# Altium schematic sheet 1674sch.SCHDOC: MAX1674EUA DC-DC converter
size 152 x 114 mm; Author: Harrylee
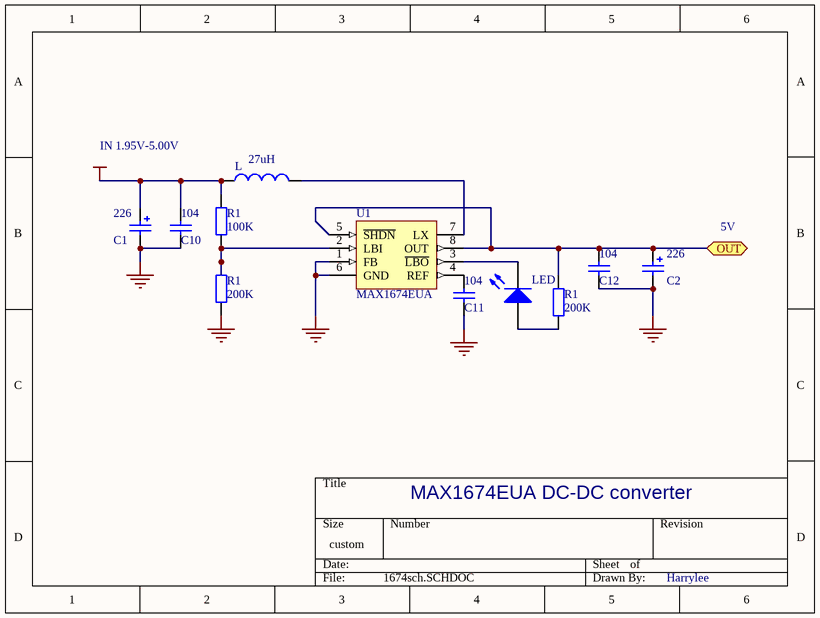
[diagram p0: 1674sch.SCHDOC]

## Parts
(Parts that share a designator on the sheet are numbered #1, #2 ... from top to bottom, then left to right.)
C1  value 226  [RB7.6-15]  (hidden comment: Cap Pol1)
C2  value 226  [RB7.6-15]  (hidden comment: Cap Pol1)
C10  value 104  [CC1310-0504]  (hidden comment: Cap Semi)
C11  value 104  [CC1310-0504]  (hidden comment: Cap Semi)
C12  value 104  [CC1310-0504]  (hidden comment: Cap Semi)
L  value 27uH  [CC4532-1812]  (hidden comment: Inductor)
LED  LED2  [DSO-F2/D6.1]  (value not drawn)
R1#1  value 100K  [AXIAL-0.4]  (hidden comment: Res2)
R1#2  value 200K  [AXIAL-0.4]  (hidden comment: Res2)
R1#3  value 200K  [AXIAL-0.4]  (hidden comment: Res2)
U1  MAX1674EUA  [UMAX8]

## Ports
OUT

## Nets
GND: C1.2 C2.2 C10.1 C11.1 C12.1 R1#2.1 U1.1(FB) U1.6(GND)
VCC: C1.1 C10.2 L.1 R1#1.1
OUT: C2.1 C12.2 R1#3.2 U1.5(~{SHDN}) U1.8(OUT) ; port OUT
NetC11_2: C11.2 U1.4(REF)
NetL_2: L.2 U1.7(LX)
NetLED_1: LED.1(A) R1#3.1
NetLED_2: LED.2(K) U1.3(~{LBO})
NetR1#1_2: R1#1.2 R1#2.2 U1.2(LBI)

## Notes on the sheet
- IN 1.95V-5.00V
- 5V
- MAX1674EUA DC-DC converter
- Harrylee

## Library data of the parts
C1 C2 = Cap Pol1: Polarized Capacitor (Radial)
C10-C12 = Cap Semi: Capacitor (Semiconductor SIM Model)
LED = LED2: Typical RED, GREEN, YELLOW, AMBER GaAs LED
R1#1-R1#3 = Res2: Resistor
U1 = MAX1674EUA: High-Efficiency, Low-Supply-Current, Compact, Step-Up DC-DC Converter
